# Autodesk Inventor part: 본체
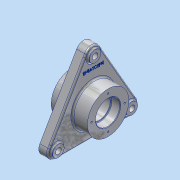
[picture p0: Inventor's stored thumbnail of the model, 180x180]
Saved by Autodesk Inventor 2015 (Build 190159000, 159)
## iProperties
Created: 2023-04
Part Number: 본체
Material: 알루미늄 6061
Document SubType Name: Modeling
Designer: SCD-A04
Density: 2.7 g/cm^3
Appearance: 알루미늄 - 평지
Author: SCD-A04
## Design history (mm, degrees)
sketch "스케치5"
  geometry: L1 (-13.856, 90)-(-84.87, -33); L2 (-71.014, -57)-(71.014, -57); L3 (84.87, -33)-(13.856, 90); A1 r 82 centre (0, 0) between (0, 82) and (71.014, -41); A2 r 16 centre (0, 82) between (13.856, 90) and (-13.856, 90); A3 r 16 centre (71.014, -41) between (71.014, -57) and (84.87, -33); A4 r 16 centre (-71.014, -41) between (-84.87, -33) and (-71.014, -57); 1 further point
  constraints: 9 point on circle, 6 end point, 6 tangent, 4 centre point, 2 equal length, 2 equal radius, 1 coincident, 1 horizontal
  dimensions: "d3" = 164 diameter of A1; "d4" = 16 radius of A2
extrude "돌출1" new body sketch "스케치5" stored distance "d5" = 18; taper "d6" = 0 deg
sketch "스케치7"
  geometry: C1 r 82 at (0, 0); C2 r 11 at (-82, 0); C3 r 11 at (41, -71.014); C4 r 11 at (41, 71.014); A1 r 16 centre (41, -71.014) between (33, -84.87) and (57, -71.014) reference; A2 r 16 centre (41, 71.014) between (57, 71.014) and (33, 84.87) reference; A3 r 16 centre (-82, 0) between (-90, 13.856) and (-90, -13.856) reference; 1 further point
  constraints: 4 centre point, 4 coincident
  dimensions: "d7" = 164 diameter of C1; "d10" = 22 diameter of C2; "d11" = 22 diameter of C3; "d12" = 22 diameter of C4
extrude "돌출2" join sketch "스케치7" distance "d13" = 4; taper "d14" = 0 deg
sketch "스케치8"
  geometry: C1 r 40 at (0, 0); 1 further point
  constraints: 1 centre point, 1 coincident
  dimensions: "d15" = 80 diameter of C1
extrude "돌출3" join sketch "스케치8" distance "d16" = 29; taper "d17" = 0 deg
sketch "스케치9"
  geometry: C1 r 40 at (0, 0); 1 further point
  constraints: 1 centre point, 1 coincident
  dimensions: "d18" = 80 diameter of C1
extrude "돌출4" join sketch "스케치9" distance "d19" = 23; taper "d20" = 0 deg
sketch "스케치10"
  geometry: C1 r 40 at (0, 0) reference; C2 r 45 at (0, 0)
  constraints: 1 centre point, 1 coincident
  dimensions: "d21" = 90 diameter of C2
extrude "돌출5" join sketch "스케치10" distance "d22" = 5; taper "d23" = 0 deg
hole "구멍1" diameter "d26" = 42; stored, may be unused: countersink angle "d30" = 90 deg, drill point angle "d32" = 0 deg; dims "d24" = 10, "d25" = 10, "d27" = 15.875, "d28" = 47, "d29" = 17, "d31" = 8
hole "구멍2" diameter "d35" = 42; stored, may be unused: countersink angle "d39" = 90 deg, drill point angle "d41" = 0 deg; dims "d33" = 10, "d34" = 10, "d36" = 15.875, "d37" = 47, "d38" = 17, "d40" = 8
sketch "스케치11"
  geometry: L1 (0, 0)-(-32, 0); C1 r 40 at (0, 0) reference
  constraints: 2 end point, 1 horizontal
  dimensions: "d43" = 32 distance of L1.start L1.end
hole "구멍3" sketch "스케치11" at (-32, 0) diameter "d44" = 3.242; stored, may be unused: countersink angle "d48" = 90 deg, drill point angle "d50" = 118 deg; dims "d45" = 8, "d46" = 19.05, "d47" = 4.775, "d49" = 10
sketch "스케치12"
  geometry: L1 (0, 0)-(32, 0); C1 r 40 at (0, 0) reference
  constraints: 2 end point, 1 horizontal
  dimensions: "d54" = 32 distance of L1.start L1.end
hole "구멍4" sketch "스케치12" at (32, 0) diameter "d55" = 3.242; stored, may be unused: countersink angle "d59" = 90 deg, drill point angle "d61" = 118 deg; dims "d56" = 8, "d57" = 19.05, "d58" = 4.775, "d60" = 10
sketch "스케치14"
  geometry: C1 r 11 at (0, 0) reference; C2 r 5.5 at (0, 0); 1 further point
  constraints: 1 centre point, 1 coincident
  dimensions: "d66" = 11 diameter of C2
hole "구멍5" sketch "스케치14" at (0, 0) diameter "d67" = 11; stored, may be unused: countersink angle "d71" = 90 deg, drill point angle "d73" = 118 deg; dims "d68" = 8, "d69" = 19.05, "d70" = 4.775, "d72" = 10
fillet "모깎기1" dims "d77" = 3
fillet "모깎기2" dims "d78" = 3
fillet "모깎기3" dims "d79" = 3
sketch "스케치15"
  geometry: C1 r 43 at (0, 0) reference; 1 further point
  constraints: 1 horizontal alignment, 1 other
  dimensions: "d80" = 60 distance of C1.centre point (-60, 0)
feature "엠보싱1" sketch "스케치15" dims "d3" = 164, "d4" = 16, "d12" = 22, "d81" = 0.5, "d82" = 0
chamfer "모따기1" distance "d83" = 1; stored, may be unused: second distance "d84" = 2, angle "d85" = 45 deg
node "솔리드1"
pattern_circular "원형 패턴1" dims angle "d52" = 360 deg
pattern_circular "원형 패턴2" dims angle "d63" = 360 deg
pattern_circular "원형 패턴3" dims angle "d75" = 360 deg
